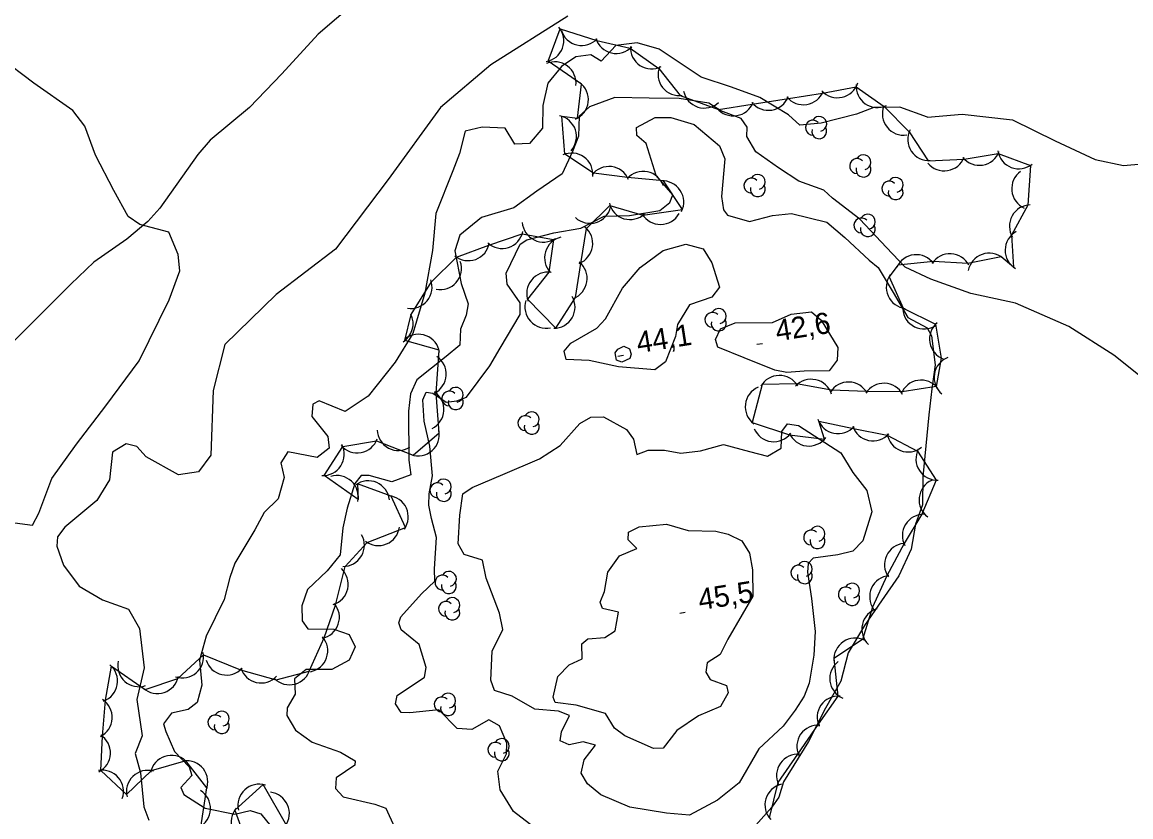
# Model space of a CAD drawing. Extents: x 646142 to 649934, y 5874075 to 5876351.
# Drawn here: x 647228 to 647384.4, y 5875630 to 5875742.1 of the extents above; entities that cross this region are included whole.
import ezdxf

# ---------------------------------------------------------------- set-up
doc = ezdxf.new("R2010")
doc.units = 0
for name, color, linetype in [('Niveau 1', 7, 'Continuous'), ('Niveau 2', 7, 'Continuous'), ('Niveau 22', 7, 'Continuous'), ('Niveau 3', 7, 'Continuous'), ('Niveau 44', 7, 'Continuous')]:
    doc.layers.add(name, color=color, linetype=linetype)

msp = doc.modelspace()

# ---------------------------------------------------------------- linework, layer by layer
at = {"layer": 'Niveau 1'}
for points in [[(647319.34, 5875716.67), (647319.74, 5875717.74), (647317.41, 5875720.48), (647316, 5875724.97), (647314.69, 5875726.1), (647314.63, 5875727.24), (647317.24, 5875728.65), (647319.47, 5875728.64), (647322.77, 5875727.66), (647326.33, 5875724.65), (647327.08, 5875722.84), (647326.63, 5875717.53), (647326.88, 5875715.61), (647327.46, 5875714.87), (647330.58, 5875713.98), (647333.82, 5875714.83), (647336.48, 5875715.1), (647341.46, 5875713.89), (647344.01, 5875711.75), (647347.42, 5875708.55), (647348.72, 5875707.48), (647350.84, 5875703.98), (647352.9, 5875700.42), (647355.62, 5875698.98), (647356.24, 5875697.85), (647356.76, 5875693.78), (647356.29, 5875690.36), (647355.85, 5875686.72), (647355, 5875677.94), (647354.98, 5875674), (647353.99, 5875671.27), (647353.37, 5875667.72), (647351.62, 5875664), (647349.17, 5875660.44), (647346.77, 5875656.99), (647344.47, 5875653.1), (647343.43, 5875649.11), (647341.29, 5875645.29), (647338.9, 5875640.6), (647335.34, 5875634.92), (647334.7, 5875632.74), (647333.7, 5875631.33)], [(647300.14, 5875628.52), (647297.29, 5875630.74), (647295.39, 5875633.8), (647295.07, 5875636.39), (647296.26, 5875638.85), (647296.34, 5875640.35), (647295.3, 5875642.81), (647293.78, 5875643.68), (647291.4, 5875642.3), (647289.33, 5875642.43), (647286.72, 5875645.07), (647282.65, 5875644.66), (647281.44, 5875644.7), (647280.63, 5875645.93), (647280.86, 5875647.1), (647284.72, 5875649.67), (647284.93, 5875651.06), (647283.98, 5875654.28), (647281.43, 5875656.36), (647281.1, 5875657.35), (647281.36, 5875658.18), (647284.3, 5875661.45), (647286.18, 5875663.25), (647286.12, 5875664.95), (647286.43, 5875669.39), (647285.7, 5875672.06), (647285.34, 5875673.96), (647285.36, 5875675.57), (647285.85, 5875678.08), (647285.49, 5875682.27), (647284.69, 5875685.79), (647284.5, 5875688.8), (647284.97, 5875689.88), (647285.9, 5875689.75), (647287.79, 5875688.51), (647289.26, 5875688.66), (647290.64, 5875689.2), (647293.92, 5875693.6), (647295.39, 5875696.09), (647295.39, 5875696.09), (647298.19, 5875700.84), (647298.19, 5875702.5), (647296.39, 5875705.12), (647296.23, 5875706.7), (647298.23, 5875710.8), (647299.14, 5875711.41), (647302.94, 5875712.37), (647306.76, 5875713.04), (647310.08, 5875714.75), (647313.62, 5875714.83), (647317.9, 5875715.55), (647319.34, 5875716.67)], [(647333.7, 5875631.33), (647331.07, 5875628.38)]]:
    msp.add_lwpolyline(points, dxfattribs=at)
at = {"layer": 'Niveau 2'}
for points in [[(647355.69, 5875728.72), (647360.58, 5875729.11), (647367.66, 5875728.34), (647373.68, 5875725.39), (647379.33, 5875722.75), (647383.31, 5875721.9), (647392.3, 5875722.7), (647402.98, 5875727.23), (647412.38, 5875731.86), (647421.2, 5875740.22), (647434.96, 5875751.95), (647440.15, 5875757.53), (647448.57, 5875764.13), (647455.88, 5875769.12), (647469.99, 5875785.6), (647476.18, 5875796.34), (647482.47, 5875807.2)], [(647304.95, 5875742.97), (647294.07, 5875736.11), (647286.95, 5875730.09), (647279.57, 5875719.91), (647272.15, 5875710.06), (647263.8, 5875703.69), (647256.57, 5875696.63), (647254.91, 5875690.14), (647254.56, 5875681.02), (647252.84, 5875678.66), (647250, 5875678.25), (647245.44, 5875680.77), (647244.14, 5875682.25), (647242.61, 5875682.61), (647240.71, 5875681.44), (647240.29, 5875677.55), (647238.51, 5875674.61), (647234, 5875670.87), (647232.93, 5875669.5), (647232.83, 5875668.16), (647233.79, 5875665.5), (647235.98, 5875662.51), (647239.28, 5875660.61), (647242.98, 5875659.26), (647244.52, 5875656.55), (647245.19, 5875650.99), (647244.14, 5875646.51), (647244.88, 5875641.42), (647243.92, 5875638.91), (647244.65, 5875636.17), (647245.13, 5875631.4), (647245.83, 5875629.52)], [(647355.69, 5875728.72), (647351.77, 5875730.1), (647348.1, 5875730.07), (647345.67, 5875729.14), (647340.68, 5875727.88), (647337.67, 5875727.57), (647336.04, 5875729.02), (647332.01, 5875731.48), (647328.01, 5875732.96), (647323.74, 5875734.37), (647317.84, 5875738.3), (647314.71, 5875739.19), (647311.71, 5875738.83), (647309.63, 5875736.6), (647308.16, 5875737.49), (647306.07, 5875737.22), (647304.02, 5875735.86), (647302.13, 5875733.49), (647301.4, 5875730.37), (647301.38, 5875727.15), (647299.52, 5875725.01), (647297.47, 5875724.91), (647296.09, 5875727.18), (647292.86, 5875727.31), (647290.45, 5875726.72), (647289.67, 5875723.6), (647288.71, 5875721.15), (647286.32, 5875715.11), (647285.86, 5875709.89), (647284.74, 5875703.86), (647283.06, 5875698.18), (647280.59, 5875694.14), (647276.76, 5875689.33), (647273.53, 5875687.17), (647269.88, 5875688.69), (647268.95, 5875688.19), (647268.84, 5875686.46), (647271.07, 5875683.65), (647271.29, 5875682), (647269.58, 5875680.68), (647265.43, 5875681.46), (647264.43, 5875679.93), (647264.93, 5875677.85), (647264.08, 5875674.84), (647262.09, 5875672.92), (647260.78, 5875670.49), (647257.98, 5875665.79), (647257.26, 5875663.76), (647256.48, 5875660.64), (647253.9, 5875655.45), (647253.9, 5875655.45), (647252.97, 5875652.08), (647253.32, 5875648.56), (647252.65, 5875646.09), (647251.37, 5875645.1), (647249.01, 5875644.62), (647247.9, 5875643.08), (647248.23, 5875642.02), (647249.43, 5875639.17), (647251.54, 5875637.03), (647251.89, 5875635.81), (647250.34, 5875634.1), (647250.78, 5875633.11), (647253.79, 5875631.19), (647257.95, 5875630.35)], [(647226.93, 5875671.44), (647229.44, 5875671.12), (647230.31, 5875672.82), (647232.13, 5875677.73), (647235.62, 5875682.58), (647239.75, 5875687.95), (647244.48, 5875694.31), (647248.69, 5875702.92), (647250.18, 5875707.04), (647249.95, 5875709.32), (647248.66, 5875712.48), (647244.57, 5875713.56), (647242.9, 5875714.71), (647240.87, 5875718.37), (647238.29, 5875723.35), (647236.79, 5875727.46), (647235.13, 5875729.65), (647229.61, 5875733.53), (647224.74, 5875737.19)], [(647352.52, 5875707.56), (647349.9, 5875710.33), (647346.13, 5875714.3), (647342.29, 5875717.29), (647341.03, 5875718.42), (647337.53, 5875719.67), (647334.65, 5875721.55), (647331.45, 5875723.81), (647330.2, 5875725.97), (647330.25, 5875727.29), (647329.38, 5875728.52), (647326.52, 5875729.61), (647324.81, 5875730.7), (647320.62, 5875731.36), (647316.43, 5875731.39), (647311.55, 5875731.47), (647308.01, 5875730.19), (647306.54, 5875728.83), (647306.42, 5875726.01), (647305.6, 5875723.86), (647304.13, 5875720.73), (647300.54, 5875718.25), (647297.33, 5875715.91), (647292.76, 5875714.53), (647289.69, 5875712.04), (647288.99, 5875709.85), (647289.9, 5875705.24), (647290.87, 5875702.36), (647290.57, 5875700.78), (647289.79, 5875698.81), (647289.68, 5875696.51), (647287.77, 5875694.94), (647283.62, 5875691.65), (647282.73, 5875689.67), (647282.46, 5875687.23), (647282.51, 5875680.31), (647282.78, 5875678.22), (647280.12, 5875677.26), (647276.89, 5875678.13), (647275.8, 5875678.13), (647274.88, 5875677.01), (647273.79, 5875673.52), (647273.2, 5875670.77), (647272.84, 5875666.95), (647271, 5875664.7), (647268.22, 5875662.07), (647267.42, 5875659.75), (647267.46, 5875657.64), (647268.26, 5875656.52), (647271.93, 5875656.44), (647271.93, 5875656.44), (647274.07, 5875655.68), (647274.93, 5875653.94), (647274.09, 5875652.08), (647271.64, 5875650.74), (647268.03, 5875650.77), (647266.38, 5875649.46), (647266.48, 5875647.29), (647265.36, 5875645.35), (647265.3, 5875644.25), (647266.53, 5875642.21), (647268.88, 5875640.5), (647272.86, 5875639.08), (647274.93, 5875637.86), (647274.87, 5875637.28)], [(647320.13, 5875697.74), (647318.71, 5875694.17), (647317.22, 5875693.05), (647312.09, 5875693.49), (647307.95, 5875694.38), (647304.68, 5875694.51), (647304.4, 5875695.68), (647305.37, 5875696.8), (647309.04, 5875698.95), (647310.23, 5875700.27), (647312.66, 5875704.57), (647315.16, 5875707.51), (647318.36, 5875709.89), (647321.58, 5875710.79), (647324.04, 5875710.13), (647325.27, 5875708.14), (647326.35, 5875704.71), (647325.23, 5875703.29), (647322.08, 5875702.22), (647320.42, 5875699.43), (647320.13, 5875697.74)], [(647396.68, 5875685.68), (647391.27, 5875687.7), (647381.97, 5875695.11), (647375.62, 5875699.16), (647368.08, 5875702.45), (647361.77, 5875703.81), (647356.12, 5875705.87), (647352.52, 5875707.56)], [(647334.12, 5875693), (647329.79, 5875694.73), (647326.1, 5875696.24), (647325.76, 5875697.34), (647326.47, 5875698.84), (647328.56, 5875699.69), (647333.81, 5875699.71), (647336.43, 5875700.89), (647339.31, 5875701.24), (647340.68, 5875700.07), (647343, 5875696.19), (647342.95, 5875694.42), (647341.78, 5875692.93), (647338.25, 5875692.85), (647335.81, 5875692.66), (647334.12, 5875693)], [(647313.68, 5875694.66), (647312.56, 5875694.15), (647311.79, 5875694.41), (647311.63, 5875695.45), (647312.01, 5875695.97), (647312.82, 5875696.37), (647313.63, 5875696), (647313.88, 5875695.25), (647313.68, 5875694.66)], [(647295.75, 5875678.26), (647300.96, 5875680.5), (647303.85, 5875682.39), (647306.63, 5875685.47), (647308.2, 5875686.38), (647309.96, 5875686.44), (647313.23, 5875684.61), (647314.22, 5875683.28), (647314.66, 5875681.1), (647316.25, 5875681.72), (647318.59, 5875681.73), (647320.86, 5875681.28), (647323.63, 5875681.62), (647326.91, 5875682.52), (647330.55, 5875681.53), (647333.12, 5875680.88), (647335.01, 5875681.98), (647335.12, 5875684.33), (647335.92, 5875685.44), (647337.49, 5875685.2), (647343.46, 5875681.36), (647345.16, 5875678.57), (647347.12, 5875676.03), (647347.82, 5875673.02), (647346.57, 5875668.9), (647345.12, 5875667.44), (647343, 5875666.94), (647339.56, 5875666.47), (647338.84, 5875665.71), (647338.73, 5875664.51), (647339.32, 5875660.8), (647339.84, 5875656.12), (647339.65, 5875652.8), (647338.96, 5875648.85), (647338.28, 5875647.01), (647337, 5875645)], [(647337, 5875645), (647335.33, 5875642.77), (647331.88, 5875639.57), (647329.1, 5875634.78), (647326.04, 5875632.3), (647322.08, 5875630.19), (647318.86, 5875630.48), (647313.7, 5875631.32), (647309.59, 5875633.07), (647307.72, 5875634.64), (647306.83, 5875636.15), (647307.22, 5875638.01), (647308.84, 5875640.06), (647307.08, 5875640.56), (647305.12, 5875640.13), (647303.87, 5875640.69), (647304.03, 5875641.96), (647305.17, 5875644.25), (647303.62, 5875644.89), (647300.29, 5875645.17), (647297.08, 5875647.01), (647294.6, 5875647.78), (647294.06, 5875649.27), (647294.28, 5875653.34), (647295.75, 5875656.4), (647295.29, 5875658.69), (647293.43, 5875663.64), (647292.89, 5875666.21), (647290.3, 5875666.97), (647289.47, 5875668.48), (647289.69, 5875672.56), (647290.14, 5875675.57), (647291.42, 5875676.44), (647295.75, 5875678.26)], [(647327.54, 5875669.88), (647329.46, 5875668.94), (647330.54, 5875667.17), (647331, 5875664.83), (647331.02, 5875661.13), (647329.51, 5875658.52), (647327.52, 5875655.02), (647326.43, 5875652.86), (647324.6, 5875651.7), (647324.39, 5875650.37), (647325.01, 5875649.35), (647327.31, 5875648.51), (647327.53, 5875647.45), (647326.47, 5875645.52), (647323.35, 5875644.23), (647320.3, 5875642.15), (647318.38, 5875639.68), (647317.02, 5875639.6), (647312.97, 5875641.4), (647311.5, 5875642.5), (647310.27, 5875644.54), (647306.11, 5875645.71), (647303.16, 5875646.09), (647302.86, 5875646.86), (647303.54, 5875649.77), (647305.14, 5875651.42), (647306.94, 5875652.28), (647306.9, 5875654.39), (647307.74, 5875655.1), (647310.17, 5875655.29), (647311.62, 5875656.24), (647312.1, 5875658.85), (647309.83, 5875659.36), (647309.51, 5875660.24), (647310.1, 5875661.78), (647310.57, 5875664.5), (647312.23, 5875666.78), (647314.69, 5875667.83), (647313.43, 5875669.07), (647313.49, 5875670.16), (647315.02, 5875670.88), (647318.85, 5875671.27), (647321.9, 5875670.39), (647325.79, 5875670.27), (647327.54, 5875669.88)], [(647274.87, 5875637.28), (647272.24, 5875635.47), (647272.16, 5875633.97), (647273.26, 5875632.77), (647277.71, 5875631.74), (647279.25, 5875631.21), (647280.49, 5875628.53)], [(647257.95, 5875630.35), (647260.13, 5875630.86), (647261.62, 5875630.38), (647263.64, 5875627.9)]]:
    msp.add_lwpolyline(points, dxfattribs=at)
at = {"layer": 'Niveau 22'}
msp.add_lwpolyline([(647274.9, 5875744.84), (647269.7, 5875740.4), (647264.61, 5875734.81), (647260.01, 5875730.08), (647254.47, 5875725.48), (647252.72, 5875723.46), (647247.36, 5875715.89), (647245.71, 5875713.99), (647242.73, 5875711.5), (647238.09, 5875708.26), (647234.83, 5875705.16), (647226.65, 5875696.94)], dxfattribs=at)
at = {"layer": 'Niveau 3'}
for p, q in [((647331.61, 5875696.66), (647332.4, 5875696.79)), ((647312.01, 5875694.99), (647312.8, 5875695.11)), ((647320.71, 5875658.72), (647321.5, 5875658.84))]:
    msp.add_line(p, q, dxfattribs=at)
at = {"layer": 'Niveau 44'}
for points in [[(647298.51, 5875712.25), (647302.91, 5875711.44), (647302.27, 5875706.82), (647299.23, 5875703.04), (647303.26, 5875698.93), (647306.02, 5875703.27), (647306.78, 5875708.06), (647307.57, 5875713), (647310.88, 5875716.26), (647315.53, 5875714.88), (647321.1, 5875715.67), (647318.41, 5875719.72), (647313.36, 5875720.19), (647308.55, 5875720.81), (647304.53, 5875723.49), (647304.08, 5875728.84), (647306.29, 5875728.57), (647306.87, 5875733.39), (647302.18, 5875736.62), (647303.87, 5875741.17), (647309.01, 5875739.53), (647313.74, 5875738.44), (647317.77, 5875735.57), (647320.77, 5875731.75), (647326.17, 5875729.77), (647330.96, 5875730.53), (647336.04, 5875731.34), (647340.84, 5875732.1), (647345.59, 5875733.01), (647349.57, 5875730.23), (647353.08, 5875726.63), (647355.75, 5875722.57), (647360.85, 5875722.8), (647365.64, 5875723.57), (647370.19, 5875721.91), (647369.84, 5875716.3), (647367.52, 5875712.04), (647367.82, 5875707.53), (647366.06, 5875709.01), (647361.35, 5875708.08), (647356.5, 5875708.33), (647351.49, 5875707.8), (647350.24, 5875706.19)], [(647253.17, 5875628.51), (647254.03, 5875634.04), (647251.06, 5875637.89), (647246.18, 5875636.48), (647242.7, 5875633.1), (647239.05, 5875636.49), (647239.29, 5875641.34), (647239.74, 5875646.42), (647240.57, 5875651.21), (647245.3, 5875647.92), (647249.9, 5875649.47), (647253.55, 5875652.83), (647258.75, 5875650.72), (647263.79, 5875649.28), (647268.47, 5875650.54), (647270.58, 5875655.25), (647272.17, 5875659.84), (647273.52, 5875665.31), (647276.64, 5875668.7), (647282.05, 5875670.82), (647280.02, 5875675.23), (647275.27, 5875676.97), (647275.35, 5875674.77), (647270.56, 5875678.14), (647273.2, 5875682.22), (647277.93, 5875683.04), (647283.13, 5875680.99), (647286.8, 5875684.18), (647286.37, 5875689.77), (647286.77, 5875695.84), (647281.95, 5875697.19), (647282.82, 5875700.87), (647285.68, 5875705.48), (647289.23, 5875708.97), (647293.78, 5875710.64), (647298.51, 5875712.25)], [(647350.24, 5875706.19), (647352.23, 5875701.76), (647356.81, 5875699.49), (647357.62, 5875694.7), (647356.88, 5875690.72), (647352.09, 5875689.97), (647347, 5875690.01), (647342.15, 5875690.18), (647337.18, 5875691.06), (647332.33, 5875691), (647330.92, 5875685.64), (647336.18, 5875683.87), (647341.14, 5875683.26), (647340.33, 5875685.8), (647345.22, 5875684.79), (647349.98, 5875683.82), (647354.24, 5875681.56), (647356.88, 5875677.49), (647354.89, 5875672.66), (647352.36, 5875668.52), (647349.93, 5875663.96), (647347.9, 5875659.55), (647346.49, 5875655.01), (647342.46, 5875652.3), (647343.04, 5875647.02), (647340.26, 5875643.03), (647337.32, 5875638.81), (647334.55, 5875634.83), (647333.35, 5875629.83)], [(647265.28, 5875628.72), (647261.98, 5875634.52), (647257.94, 5875630.92)], [(647257.94, 5875630.92), (647259.6, 5875626.36)]]:
    msp.add_lwpolyline(points, dxfattribs=at)
for centre, radius, start, end in [((647301.37, 5875739.51), 3, 279.5795, 39.5575), ((647306.89, 5875741.82), 3, 197.1045, 317.0825), ((647311.77, 5875740.7), 3, 197.1045, 317.0825), ((647316.76, 5875738.52), 3, 176.6685, 296.6464), ((647303.09, 5875733.52), 3, 353.2449, 113.2229), ((647320.66, 5875734.75), 3, 158.1762, 278.1541), ((647304.83, 5875731.19), 3, 293.147, 53.125), ((647342.97, 5875734.45), 3, 222.6804, 342.6583), ((647348.59, 5875733.07), 3, 175.1458, 295.1238), ((647324.19, 5875733), 3, 192.2759, 312.2539), ((647333.23, 5875732.68), 3, 219.0487, 339.0266), ((647338.16, 5875733.46), 3, 219.0487, 339.0266), ((647328.29, 5875731.89), 3, 219.0487, 339.0266), ((647352.3, 5875729.17), 3, 158.9254, 278.9033), ((647303.15, 5875725.98), 3, 318.0553, 78.0332), ((647339.5, 5875727.23), 1.05, 44.1154, 269.804), ((647340.4, 5875727.76), 1.05, 282.2692, 149.7263), ((647340.4, 5875726.71), 1.05, 166.9369, 29.6212), ((647355.89, 5875725.57), 3, 153.3636, 273.3416), ((647305.47, 5875720.64), 3, 354.2568, 114.2348), ((647346.64, 5875722.35), 1.05, 282.2692, 149.7263), ((647362.97, 5875724.92), 3, 219.2098, 339.1877), ((647368.55, 5875724.42), 3, 189.2302, 309.2082), ((647345.74, 5875721.82), 1.05, 44.1154, 269.804), ((647346.64, 5875721.3), 1.05, 166.9369, 29.6212), ((647358.03, 5875724.13), 3, 219.2098, 339.1877), ((647310.73, 5875718.75), 3, 22.7018, 142.6798), ((647315.56, 5875718.07), 3, 18.1772, 138.1551), ((647331.73, 5875719.58), 1.05, 282.2692, 149.7263), ((647370.55, 5875718.61), 3, 125.6162, 245.5942), ((647318.29, 5875716.72), 3, 333.5557, 93.5337), ((647330.83, 5875719.05), 1.05, 44.1154, 269.804), ((647331.73, 5875718.53), 1.05, 166.9369, 29.6212), ((647350.28, 5875718.63), 1.05, 44.1154, 269.804), ((647351.18, 5875719.16), 1.05, 282.2692, 149.7263), ((647351.18, 5875718.11), 1.05, 166.9369, 29.6212), ((647308.05, 5875716.73), 3, 227.143, 347.1209), ((647313.71, 5875717.26), 3, 193.4452, 313.4232), ((647370.23, 5875713.33), 3, 91.365, 211.3429), ((647318.01, 5875716.57), 3, 210.7566, 330.7346), ((647346.34, 5875713.43), 1.05, 44.1154, 269.804), ((647347.24, 5875713.96), 1.05, 282.2692, 149.7263), ((647295.65, 5875713.18), 3, 227.9282, 347.9062), ((647301.49, 5875714.08), 3, 184.1985, 304.1764), ((647305.45, 5875710.88), 3, 290.9347, 50.9126), ((647347.24, 5875712.91), 1.05, 166.9369, 29.6212), ((647369.62, 5875709.93), 3, 119.0384, 239.0164), ((647290.9, 5875711.46), 3, 230.2105, 350.1885), ((647304.65, 5875708.86), 3, 103.6756, 223.6535), ((647354.08, 5875706.3), 3, 35.8491, 155.827), ((647358.84, 5875706.44), 3, 27.0246, 147.0026), ((647364.38, 5875706.52), 3, 49.8709, 169.8488), ((647286.93, 5875707.37), 3, 258.845, 18.8229), ((647304.66, 5875705.94), 3, 290.9347, 50.9126), ((647302.13, 5875703.83), 3, 81.2328, 201.2108), ((647352.85, 5875704.7), 3, 144.1084, 264.0863), ((647282.78, 5875704.71), 3, 260.7504, 20.7283), ((647302.95, 5875701.91), 3, 269.8814, 29.8594), ((647301.88, 5875701.93), 3, 162.1241, 282.102), ((647326.22, 5875700.64), 1.05, 282.2692, 149.7263), ((647355.17, 5875701.83), 3, 183.9316, 303.9095), ((647280.11, 5875699.56), 3, 301.7397, 26.5482), ((647325.32, 5875700.11), 1.05, 44.1154, 269.804), ((647326.22, 5875699.59), 1.05, 166.9369, 29.6212), ((647358.95, 5875697.39), 3, 129.6432, 249.6211), ((647283.87, 5875695.08), 3, 8.5273, 128.5052), ((647284.78, 5875692.45), 3, 296.2216, 56.1996), ((647359.6, 5875691.97), 3, 110.8925, 230.8705), ((647334.78, 5875689.26), 3, 30.7333, 150.7112), ((647289.12, 5875689.53), 1.05, 282.2692, 149.7263), ((647332.96, 5875687.84), 3, 113.1209, 233.0989), ((647339.27, 5875688.72), 3, 17.7387, 137.7166), ((647344.51, 5875688.33), 3, 27.9797, 147.9576), ((647349.51, 5875688.16), 3, 27.9797, 147.9576), ((647354.76, 5875688.6), 3, 38.8206, 158.7985), ((647284.45, 5875687.46), 3, 296.2216, 56.1996), ((647288.22, 5875689), 1.05, 44.1154, 269.804), ((647289.12, 5875688.48), 1.05, 166.9369, 29.6212), ((647298.94, 5875685.53), 1.05, 44.1154, 269.804), ((647299.84, 5875686.06), 1.05, 282.2692, 149.7263), ((647343.06, 5875687.04), 3, 198.403, 318.381), ((647281.04, 5875684.66), 3, 182.1378, 302.1158), ((647283.81, 5875683.92), 3, 250.9808, 10.9588), ((647299.84, 5875685.01), 1.05, 166.9369, 29.6212), ((647333.98, 5875685.91), 3, 203.0957, 323.0737), ((647347.96, 5875686.03), 3, 198.403, 318.381), ((647275.22, 5875684.33), 3, 220.6135, 340.5914), ((647338.94, 5875685.3), 3, 203.0957, 323.0737), ((647352.95, 5875684.46), 3, 188.6432, 308.6211), ((647270.4, 5875681.14), 3, 267.0724, 27.0504), ((647357.04, 5875680.48), 3, 152.9062, 272.8842), ((647272.37, 5875675.13), 3, 347.0431, 107.021), ((647276.79, 5875674.39), 3, 6.4158, 126.3938), ((647286.53, 5875676.05), 1.05, 44.1154, 269.804), ((647287.43, 5875676.58), 1.05, 282.2692, 149.7263), ((647357.48, 5875674.71), 3, 113.8111, 233.7891), ((647279.43, 5875672.29), 3, 324.7123, 84.6902), ((647287.43, 5875675.53), 1.05, 166.9369, 29.6212), ((647355.13, 5875669.67), 3, 88.5356, 208.5136), ((647278.21, 5875671.25), 3, 232.3862, 352.3641), ((647339.25, 5875669.39), 1.05, 44.1154, 269.804), ((647340.15, 5875669.92), 1.05, 282.2692, 149.7263), ((647273.23, 5875668.3), 3, 269.5662, 29.5441), ((647340.15, 5875668.87), 1.05, 166.9369, 29.6212), ((647352.6, 5875665.56), 3, 95.3307, 215.3087), ((647337.46, 5875664.43), 1.05, 44.1154, 269.804), ((647338.36, 5875664.96), 1.05, 282.2692, 149.7263), ((647270.96, 5875662.79), 3, 287.2578, 47.2357), ((647287.26, 5875663.03), 1.05, 44.1154, 269.804), ((647288.16, 5875663.56), 1.05, 282.2692, 149.7263), ((647338.36, 5875663.91), 1.05, 166.9369, 29.6212), ((647350.51, 5875661.02), 3, 95.3307, 215.3087), ((647288.16, 5875662.51), 1.05, 166.9369, 29.6212), ((647344.14, 5875661.36), 1.05, 44.1154, 269.804), ((647345.04, 5875661.89), 1.05, 282.2692, 149.7263), ((647288.64, 5875659.85), 1.05, 282.2692, 149.7263), ((647345.04, 5875660.84), 1.05, 166.9369, 29.6212), ((647269.71, 5875658.13), 3, 280.82, 40.798), ((647287.74, 5875659.32), 1.05, 44.1154, 269.804), ((647288.64, 5875658.8), 1.05, 166.9369, 29.6212), ((647349.4, 5875656.46), 3, 106.8673, 226.8452), ((647268.07, 5875653.4), 3, 280.82, 40.798), ((647345.46, 5875652.19), 3, 63.9362, 183.9142), ((647250.56, 5875652.57), 3, 250.9907, 10.9687), ((647238.42, 5875649.11), 3, 290.2497, 50.2276), ((647244.43, 5875651.33), 3, 168.3408, 288.3187), ((647256.78, 5875652.98), 3, 197.0984, 317.0763), ((647344.88, 5875649.49), 3, 126.9449, 246.9229), ((647261.66, 5875651.86), 3, 197.0471, 317.025), ((647265.67, 5875651.61), 3, 225.0533, 345.0313), ((647247.04, 5875650.37), 3, 228.5395, 348.5174), ((647287.14, 5875645.83), 1.05, 44.1154, 269.804), ((647288.04, 5875646.36), 1.05, 282.2692, 149.7263), ((647343.1, 5875644.02), 3, 85.1558, 205.1337), ((647237.66, 5875643.99), 3, 297.1449, 57.1229), ((647288.04, 5875645.31), 1.05, 166.9369, 29.6212), ((647255.21, 5875643.29), 1.05, 44.1154, 269.804), ((647256.11, 5875643.82), 1.05, 282.2692, 149.7263), ((647256.11, 5875642.77), 1.05, 166.9369, 29.6212), ((647340.24, 5875639.92), 3, 85.1558, 205.1337), ((647237.41, 5875639), 3, 297.1449, 57.1229), ((647294.72, 5875639.44), 1.05, 44.1154, 269.804), ((647295.62, 5875639.97), 1.05, 282.2692, 149.7263), ((647295.62, 5875638.92), 1.05, 166.9369, 29.6212), ((647249.03, 5875635.65), 3, 48.3618, 168.3398), ((647251.15, 5875634.89), 3, 337.6313, 97.6092), ((647337.38, 5875635.81), 3, 85.1558, 205.1337), ((647239.26, 5875633.55), 3, 340.4114, 100.3893), ((647245.67, 5875633.53), 3, 74.2186, 194.1965), ((647261.39, 5875631.58), 3, 72.6373, 192.6152), ((647335.74, 5875631.65), 3, 103.2759, 223.2539), ((647251.52, 5875631.16), 3, 297.463, 57.441), ((647262.65, 5875630.45), 3, 323.7196, 83.6976), ((647260.43, 5875629.24), 3, 139.9278, 259.9058)]:
    msp.add_arc(centre, radius, start, end, dxfattribs=at)

# ---------------------------------------------------------------- texts
at = {"layer": 'Niveau 3'}
for s, p in [('42,6 ', (647334.46, 5875697.07)), ('44,1 ', (647314.86, 5875695.4)), ('45,5 ', (647323.56, 5875659.12))]:
    msp.add_text(s, height=3, rotation=8.9405, dxfattribs=at).set_placement(p)

doc.saveas('drawing.dxf')
